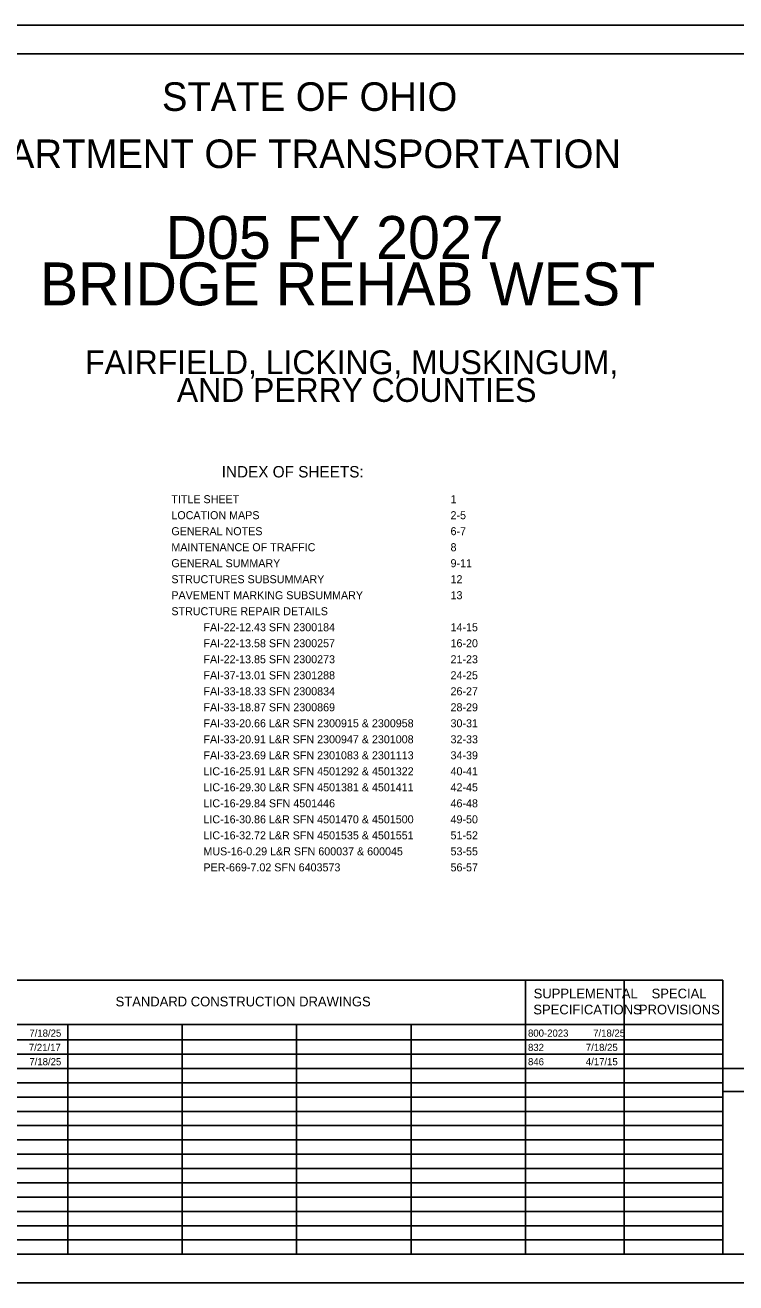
# Model space of a CAD drawing. Extents: x 0 to 34, y 0 to 22.
# Drawn here: x 11.41 to 23.83, y 0 to 22 of the extents above; entities that cross this region are included whole.
import ezdxf

# ---------------------------------------------------------------- set-up
doc = ezdxf.new("R2010")
doc.units = 0
for name, color, linetype in [('SH_Border', 7, 'Continuous'), ('SH_Cut_Line', 7, 'Continuous'), ('SH_Data', 7, 'Continuous'), ('SH_Text', 7, 'Continuous')]:
    doc.layers.add(name, color=color, linetype=linetype)

msp = doc.modelspace()

# ---------------------------------------------------------------- linework, layer by layer
at = {"layer": 'SH_Border'}
msp.add_lwpolyline([(1.5, 21.5), (33.5, 21.5), (33.5, 0.5), (1.5, 0.5)], close=True, dxfattribs=at)
at = {"layer": 'SH_Cut_Line'}
msp.add_lwpolyline([(0, 0), (34, 0), (34, 22), (0, 22)], close=True, dxfattribs=at)
at = {"layer": 'SH_Data'}
for p, q in [((10.15, 5.292), (23.6, 5.292)), ((20.15, 0.5), (20.15, 5.292)), ((21.875, 0.5), (21.875, 5.292)), ((23.6, 0.5), (23.6, 5.292)), ((10.15, 4.521), (23.6, 4.521)), ((12.15, 0.5), (12.15, 4.521)), ((14.15, 0.5), (14.15, 4.521)), ((16.15, 0.5), (16.15, 4.521)), ((18.15, 0.5), (18.15, 4.521)), ((10.15, 4.25), (23.6, 4.25)), ((10.15, 4), (23.6, 4)), ((10.15, 3.75), (23.6, 3.75)), ((23.6, 0.5), (23.6, 3.75)), ((23.6, 3.75), (26.4, 3.75)), ((10.15, 3.5), (23.6, 3.5)), ((23.6, 3.35), (26.4, 3.35)), ((10.15, 3.25), (23.6, 3.25)), ((10.15, 3), (23.6, 3)), ((10.15, 2.75), (23.6, 2.75)), ((10.15, 2.5), (23.6, 2.5)), ((10.15, 2.25), (23.6, 2.25)), ((10.15, 2), (23.6, 2)), ((10.15, 1.75), (23.6, 1.75)), ((10.15, 1.5), (23.6, 1.5)), ((10.15, 1.25), (23.6, 1.25)), ((10.15, 1), (23.6, 1)), ((10.15, 0.75), (23.6, 0.75)), ((23.6, 0.5), (26.4, 0.5))]:
    msp.add_line(p, q, dxfattribs=at)

# ---------------------------------------------------------------- texts
at = {"layer": 'SH_Text'}
for s, height, p in [('STATE OF OHIO', 0.5, (13.795, 20.5)), ('DEPARTMENT OF TRANSPORTATION', 0.5, (9.747, 19.5)), ('D05 FY 2027', 0.75, (13.859, 17.911)), ('BRIDGE REHAB WEST', 0.75, (11.662, 17.099)), ('FAIRFIELD, LICKING, MUSKINGUM,', 0.41667, (12.453, 15.895)), ('AND PERRY COUNTIES', 0.41667, (14.057, 15.41)), ('INDEX OF SHEETS:', 0.2, (14.84, 14.088)), ('TITLE SHEET', 0.14, (13.961, 13.638)), ('1', 0.14, (18.84, 13.638)), ('LOCATION MAPS', 0.14, (13.961, 13.358)), ('2-5', 0.14, (18.84, 13.358)), ('GENERAL NOTES', 0.14, (13.961, 13.078)), ('6-7', 0.14, (18.84, 13.078)), ('MAINTENANCE OF TRAFFIC', 0.14, (13.961, 12.798)), ('8', 0.14, (18.84, 12.798)), ('GENERAL SUMMARY', 0.14, (13.961, 12.518)), ('9-11', 0.14, (18.84, 12.518)), ('STRUCTURES SUBSUMMARY', 0.14, (13.961, 12.238)), ('12', 0.14, (18.84, 12.238)), ('PAVEMENT MARKING SUBSUMMARY', 0.14, (13.961, 11.958)), ('13', 0.14, (18.84, 11.958)), ('STRUCTURE REPAIR DETAILS', 0.14, (13.961, 11.678)), ('FAI-22-12.43 SFN 2300184', 0.14, (14.521, 11.398)), ('14-15', 0.14, (18.84, 11.398)), ('FAI-22-13.58 SFN 2300257', 0.14, (14.521, 11.118)), ('16-20', 0.14, (18.84, 11.118)), ('FAI-22-13.85 SFN 2300273', 0.14, (14.521, 10.838)), ('21-23', 0.14, (18.84, 10.838)), ('FAI-37-13.01 SFN 2301288', 0.14, (14.521, 10.558)), ('24-25', 0.14, (18.84, 10.558)), ('FAI-33-18.33 SFN 2300834', 0.14, (14.521, 10.278)), ('26-27', 0.14, (18.84, 10.278)), ('FAI-33-18.87 SFN 2300869', 0.14, (14.521, 9.998)), ('28-29', 0.14, (18.84, 9.998)), ('FAI-33-20.66 L&R SFN 2300915 & 2300958', 0.14, (14.521, 9.718)), ('30-31', 0.14, (18.84, 9.718)), ('FAI-33-20.91 L&R SFN 2300947 & 2301008', 0.14, (14.521, 9.438)), ('32-33', 0.14, (18.84, 9.438)), ('FAI-33-23.69 L&R SFN 2301083 & 2301113', 0.14, (14.521, 9.158)), ('34-39', 0.14, (18.84, 9.158)), ('LIC-16-25.91 L&R SFN 4501292 & 4501322', 0.14, (14.521, 8.878)), ('40-41', 0.14, (18.84, 8.878)), ('LIC-16-29.30 L&R SFN 4501381 & 4501411', 0.14, (14.521, 8.598)), ('42-45', 0.14, (18.84, 8.598)), ('LIC-16-29.84 SFN 4501446', 0.14, (14.521, 8.318)), ('46-48', 0.14, (18.84, 8.318)), ('LIC-16-30.86 L&R SFN 4501470 & 4501500', 0.14, (14.521, 8.038)), ('49-50', 0.14, (18.84, 8.038)), ('LIC-16-32.72 L&R SFN 4501535 & 4501551', 0.14, (14.521, 7.758)), ('51-52', 0.14, (18.84, 7.758)), ('MUS-16-0.29 L&R SFN 600037 & 600045', 0.14, (14.521, 7.478)), ('53-55', 0.14, (18.84, 7.478)), ('PER-669-7.02 SFN 6403573', 0.14, (14.521, 7.198)), ('56-57', 0.14, (18.84, 7.198)), ('SUPPLEMENTAL', 0.17, (20.293, 4.976)), ('SPECIAL', 0.17, (22.354, 4.976)), ('STANDARD CONSTRUCTION DRAWINGS', 0.17, (12.986, 4.836)), ('SPECIFICATIONS', 0.17, (20.287, 4.696)), ('PROVISIONS', 0.17, (22.132, 4.696)), ('7/18/25', 0.125, (11.479, 4.306)), ('800-2023', 0.125, (20.194, 4.306)), ('7/18/25', 0.125, (21.333, 4.306)), ('7/21/17', 0.125, (11.47, 4.056)), ('832', 0.125, (20.194, 4.056)), ('7/18/25', 0.125, (21.204, 4.056)), ('7/18/25', 0.125, (11.479, 3.806)), ('846', 0.125, (20.194, 3.806)), ('4/17/15', 0.125, (21.204, 3.806))]:
    msp.add_text(s, height=height, dxfattribs=at).set_placement(p)

doc.saveas('drawing.dxf')
